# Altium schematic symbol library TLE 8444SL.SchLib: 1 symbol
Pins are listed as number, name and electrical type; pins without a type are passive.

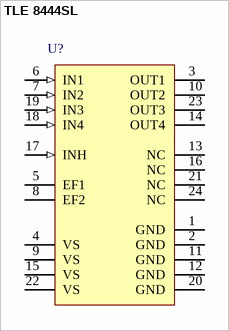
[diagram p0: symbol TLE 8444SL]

## TLE 8444SL
designator U?
Quad Half-Bridge Driver IC, -40 to 150 degC, PG-SSOP-24-7, Reel, Green; Manufacturer: Infineon; PartNumber: TLE 8444SL; Green: TRUE; Group: Stepper Motor Driver; IPeak: 4 x 0.8 A; Iq: 4 x 0.5 A; Iq (typ): 1 uA; Operating Range: 8 to 18 V; Protect: OT, OV, OL, OC
footprint INF-PG-SSOP-24-7_N (SOP, 24-Leads, Body 8.65x3.9mm, Pitch 0.65mm, IPC Medium Density)
footprint INF-PG-SSOP-24-7_L (SOP, 24-Leads, Body 8.65x3.9mm, Pitch 0.65mm, IPC High Density)
footprint INF-PG-SSOP-24-7_M (SOP, 24-Leads, Body 8.65x3.9mm, Pitch 0.65mm, IPC Low Density)
pins: 1 GND (power) "Ground; Signal ground; All GND pins must be externally connected together to the common GND potential", 2 GND (power) "Ground; Signal ground; All GND pins must be externally connected together to the common GND potential", 3 OUT1 (power) "Power Output of Half-bridge 1; Short circuit protected; with integrated free-wheeling diodes", 4 VS (power) "Power Supply Voltage; All VS pins must be externally connected together to the Battery Voltage with Reverse protection Diode, buffer capacitance and Filter against EMC. See Application Diagram.", 5 EF1 (oc) "Error Flag 1 (Diagnosis Output); Open drain by default; Low = error", 6 IN1 (in) "Input Channel of Half-bridge 1; Controls OUT1, Non-inverting Intput with internal Pull Down", 7 IN2 (in) "Input Channel of Half-bridge 2; Controls OUT2, Inverting Intput with internal Pull Up", 8 EF2 (oc) "Error Flag 2 (Diagnosis Output); Open drain by default; Low = error", 9 VS (power) "Power Supply Voltage; All VS pins must be externally connected together to the Battery Voltage with Reverse protection Diode, buffer capacitance and Filter against EMC. See Application Diagram.", 10 OUT2 (power) "Power Output of Half-bridge 2; Short circuit protected; with integrated free-wheeling diodes", 11 GND (power) "Ground; Signal ground; All GND pins must be externally connected together to the common GND potential", 12 GND (power) "Ground; Signal ground; All GND pins must be externally connected together to the common GND potential", 13 NC "Not Connected", 14 OUT4 (power) "Power Output of Half-bridge 4; Short circuit protected; with integrated free-wheeling diodes", 15 VS (power) "Power Supply Voltage; All VS pins must be externally connected together to the Battery Voltage with Reverse protection Diode, buffer capacitance and Filter against EMC. See Application Diagram.", 16 NC "Not Connected", 17 INH (in) "Inhibit Input; Low = Device in sleep mode", 18 IN4 (in) "Input Channel of Half-bridge 4; Controls OUT4, Inverting Input with internal Pull Up", 19 IN3 (in) "Input Channel of Half-bridge 3; Controls OUT3, Non-inverting Intput with internal Pull Down", 20 GND (power) "Ground; Signal ground; All GND pins must be externally connected together to the common GND potential", 21 NC "Not Connected", 22 VS (power) "Power Supply Voltage; All VS pins must be externally connected together to the Battery Voltage with Reverse protection Diode, buffer capacitance and Filter against EMC. See Application Diagram.", 23 OUT3 (power) "Power Output of Half-bridge 3; Short-circuit protected; with integrated free-wheeling diodes", 24 NC "Not Connected"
